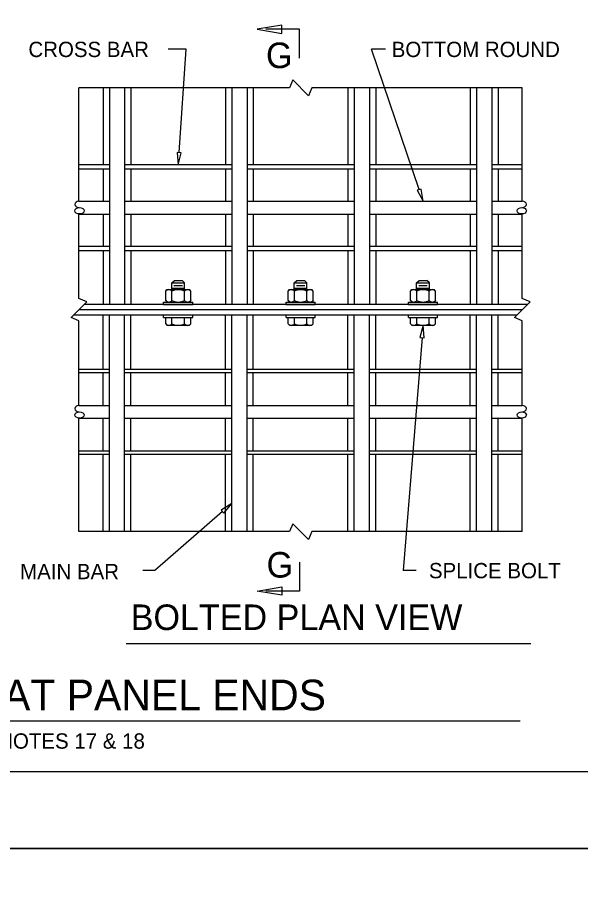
# Model space of a CAD drawing. Extents: x -24512 to -22484, y 4569 to 6351.
# Drawn here: x -23876.1 to -23765.7, y 5155.5 to 5325.8 of the extents above; entities that cross this region are included whole.
import ezdxf

# ---------------------------------------------------------------- set-up
doc = ezdxf.new("R2010")
doc.units = 0
for name, color, linetype in [('10', 7, 'Continuous'), ('2', 7, 'Continuous'), ('3', 7, 'Continuous'), ('4', 7, 'Continuous'), ('9', 7, 'Continuous'), ('PLT-BNDY', 7, 'Continuous')]:
    doc.layers.add(name, color=color, linetype=linetype)

msp = doc.modelspace()

# ---------------------------------------------------------------- linework, layer by layer
at = {"layer": '10'}
for p, q in [((-23775.46, 5203.08), (-23854.84, 5203.08)), ((-23777.59, 5187.94), (-23954.81, 5187.94))]:
    msp.add_line(p, q, dxfattribs=at)
for centre, major_axis, start_param, end_param in [((-23863.97, 5289.2), (0.895, 0), 1.692197, 4.591233), ((-23777.24, 5289.2), (-0.895, 0), 1.691952, 4.590988), ((-23863.97, 5249.2), (0.895, 0), 1.692197, 4.591233), ((-23777.24, 5249.2), (-0.895, 0), 1.691952, 4.590988)]:
    msp.add_ellipse(centre, major_axis=major_axis, ratio=0.699516, start_param=start_param, end_param=end_param, dxfattribs=at)
for centre, major_axis in [((-23863.97, 5287.95), (0.895, 0)), ((-23777.24, 5287.95), (-0.895, 0)), ((-23863.97, 5247.95), (0.895, 0)), ((-23777.24, 5247.95), (-0.895, 0))]:
    msp.add_ellipse(centre, major_axis=major_axis, ratio=0.699516, dxfattribs=at)
at = {"layer": '2'}
msp.add_line((-23353.75, 5178.04), (-24137.79, 5178.04), dxfattribs=at)
at = {"layer": '3'}
for points in [[(-23824.31, 5322.71), (-23824.31, 5324.33), (-23829.16, 5323.52)], [(-23824.31, 5214.25), (-23824.31, 5212.63), (-23829.16, 5213.44)]]:
    msp.add_lwpolyline(points, close=True, dxfattribs=at)
for points in [[(-23820.85, 5317.86), (-23820.85, 5323.52), (-23827.44, 5323.52)], [(-23820.85, 5219.1), (-23820.85, 5213.44), (-23827.44, 5213.44)]]:
    msp.add_lwpolyline(points, dxfattribs=at)
at = {"layer": '4'}
for p, q in [((-23864.08, 5289.82), (-23864.08, 5312.04)), ((-23859.32, 5312.04), (-23859.32, 5296.94)), ((-23858.09, 5312.04), (-23858.09, 5269.57)), ((-23855.12, 5312.04), (-23855.12, 5269.57)), ((-23853.89, 5312.04), (-23853.89, 5296.94)), ((-23835.33, 5312.04), (-23835.33, 5296.94)), ((-23834.09, 5312.04), (-23834.09, 5269.57)), ((-23831.12, 5312.04), (-23831.12, 5269.57)), ((-23829.89, 5312.04), (-23829.89, 5296.94)), ((-23811.33, 5312.04), (-23811.33, 5296.94)), ((-23810.09, 5312.04), (-23810.09, 5269.57)), ((-23807.12, 5312.04), (-23807.12, 5269.57)), ((-23805.89, 5312.04), (-23805.89, 5296.94)), ((-23787.33, 5312.04), (-23787.33, 5296.94)), ((-23786.09, 5312.04), (-23786.09, 5269.57)), ((-23783.12, 5312.04), (-23783.12, 5269.57)), ((-23781.89, 5312.04), (-23781.89, 5296.94)), ((-23777.14, 5289.82), (-23777.14, 5312.04)), ((-23858.09, 5296.94), (-23864.08, 5296.94)), ((-23834.09, 5296.94), (-23855.12, 5296.94)), ((-23810.09, 5296.94), (-23831.12, 5296.94)), ((-23786.09, 5296.94), (-23807.12, 5296.94)), ((-23777.14, 5296.94), (-23783.12, 5296.94)), ((-23864.08, 5296.19), (-23858.09, 5296.19)), ((-23859.32, 5296.19), (-23859.32, 5289.82)), ((-23855.12, 5296.19), (-23834.09, 5296.19)), ((-23853.89, 5296.19), (-23853.89, 5289.82)), ((-23835.33, 5296.19), (-23835.33, 5289.82)), ((-23831.12, 5296.19), (-23810.09, 5296.19)), ((-23829.89, 5296.19), (-23829.89, 5289.82)), ((-23811.33, 5296.19), (-23811.33, 5289.82)), ((-23807.12, 5296.19), (-23786.09, 5296.19)), ((-23805.89, 5296.19), (-23805.89, 5289.82)), ((-23787.33, 5296.19), (-23787.33, 5289.82)), ((-23783.12, 5296.19), (-23777.14, 5296.19)), ((-23781.89, 5296.19), (-23781.89, 5289.82)), ((-23864.08, 5289.82), (-23858.09, 5289.82)), ((-23855.12, 5289.82), (-23834.09, 5289.82)), ((-23831.12, 5289.82), (-23810.09, 5289.82)), ((-23807.12, 5289.82), (-23786.09, 5289.82)), ((-23783.12, 5289.82), (-23777.14, 5289.82)), ((-23864.08, 5287.32), (-23858.09, 5287.32)), ((-23859.32, 5287.32), (-23859.32, 5280.95)), ((-23855.12, 5287.32), (-23834.09, 5287.32)), ((-23853.89, 5287.32), (-23853.89, 5280.95)), ((-23835.33, 5287.32), (-23835.33, 5280.95)), ((-23831.12, 5287.32), (-23810.09, 5287.32)), ((-23829.89, 5287.32), (-23829.89, 5280.95)), ((-23811.33, 5287.32), (-23811.33, 5280.95)), ((-23807.12, 5287.32), (-23786.09, 5287.32)), ((-23805.89, 5287.32), (-23805.89, 5280.95)), ((-23787.33, 5287.32), (-23787.33, 5280.95)), ((-23783.12, 5287.32), (-23777.14, 5287.32)), ((-23781.89, 5287.32), (-23781.89, 5280.95)), ((-23858.09, 5280.95), (-23864.08, 5280.95)), ((-23864.08, 5280.2), (-23858.09, 5280.2)), ((-23859.32, 5280.2), (-23859.32, 5269.57)), ((-23834.09, 5280.95), (-23855.12, 5280.95)), ((-23855.12, 5280.2), (-23834.09, 5280.2)), ((-23853.89, 5280.2), (-23853.89, 5269.57)), ((-23835.33, 5280.2), (-23835.33, 5269.57)), ((-23810.09, 5280.95), (-23831.12, 5280.95)), ((-23831.12, 5280.2), (-23810.09, 5280.2)), ((-23829.89, 5280.2), (-23829.89, 5269.57)), ((-23811.33, 5280.2), (-23811.33, 5269.57)), ((-23786.09, 5280.95), (-23807.12, 5280.95)), ((-23807.12, 5280.2), (-23786.09, 5280.2)), ((-23805.89, 5280.2), (-23805.89, 5269.57)), ((-23787.33, 5280.2), (-23787.33, 5269.57)), ((-23777.14, 5280.95), (-23783.12, 5280.95)), ((-23783.12, 5280.2), (-23777.14, 5280.2)), ((-23781.89, 5280.2), (-23781.89, 5269.57)), ((-23845.86, 5273.82), (-23845.36, 5274.32)), ((-23845.36, 5274.32), (-23843.86, 5274.32)), ((-23843.36, 5273.82), (-23843.86, 5274.32)), ((-23821.86, 5273.82), (-23821.36, 5274.32)), ((-23821.36, 5274.32), (-23819.86, 5274.32)), ((-23819.36, 5273.82), (-23819.86, 5274.32)), ((-23797.86, 5273.82), (-23797.36, 5274.32)), ((-23797.36, 5274.32), (-23795.86, 5274.32)), ((-23795.36, 5273.82), (-23795.86, 5274.32)), ((-23847.06, 5272.18), (-23846.81, 5272.51)), ((-23846.81, 5272.51), (-23842.41, 5272.51)), ((-23845.86, 5273.82), (-23843.36, 5273.82)), ((-23845.86, 5272.51), (-23845.86, 5273.82)), ((-23845.86, 5272.82), (-23843.36, 5272.82)), ((-23845.44, 5273.32), (-23843.77, 5273.32)), ((-23843.36, 5272.51), (-23843.36, 5273.82)), ((-23842.15, 5272.18), (-23842.41, 5272.51)), ((-23823.06, 5272.18), (-23822.81, 5272.51)), ((-23822.81, 5272.51), (-23818.41, 5272.51)), ((-23821.86, 5272.51), (-23821.86, 5273.82)), ((-23821.86, 5273.82), (-23819.36, 5273.82)), ((-23821.86, 5272.82), (-23819.36, 5272.82)), ((-23821.44, 5273.32), (-23819.78, 5273.32)), ((-23819.36, 5272.51), (-23819.36, 5273.82)), ((-23818.15, 5272.18), (-23818.41, 5272.51)), ((-23799.06, 5272.18), (-23798.81, 5272.51)), ((-23798.81, 5272.51), (-23794.41, 5272.51)), ((-23797.86, 5273.82), (-23795.36, 5273.82)), ((-23797.86, 5272.51), (-23797.86, 5273.82)), ((-23797.86, 5272.82), (-23795.36, 5272.82)), ((-23797.44, 5273.32), (-23795.78, 5273.32)), ((-23795.36, 5272.51), (-23795.36, 5273.82)), ((-23794.15, 5272.18), (-23794.41, 5272.51)), ((-23847.06, 5270.39), (-23847.06, 5272.18)), ((-23845.83, 5270.39), (-23845.83, 5272.18)), ((-23843.38, 5270.39), (-23843.38, 5272.18)), ((-23842.15, 5270.39), (-23842.15, 5272.18)), ((-23823.06, 5270.39), (-23823.06, 5272.18)), ((-23821.83, 5270.39), (-23821.83, 5272.18)), ((-23819.38, 5270.39), (-23819.38, 5272.18)), ((-23818.15, 5270.39), (-23818.15, 5272.18)), ((-23799.06, 5270.39), (-23799.06, 5272.18)), ((-23797.83, 5270.39), (-23797.83, 5272.18)), ((-23795.38, 5270.39), (-23795.38, 5272.18)), ((-23794.15, 5270.39), (-23794.15, 5272.18)), ((-23776.14, 5269.57), (-23863.08, 5269.57)), ((-23847.47, 5269.57), (-23847.47, 5270.07)), ((-23847.47, 5270.07), (-23841.74, 5270.07)), ((-23847.47, 5269.57), (-23841.74, 5269.57)), ((-23847.06, 5270.39), (-23846.81, 5270.07)), ((-23846.81, 5270.07), (-23842.41, 5270.07)), ((-23842.15, 5270.39), (-23842.41, 5270.07)), ((-23841.74, 5269.57), (-23841.74, 5270.07)), ((-23823.47, 5270.07), (-23817.74, 5270.07)), ((-23823.47, 5269.57), (-23823.47, 5270.07)), ((-23823.47, 5269.57), (-23817.74, 5269.57)), ((-23823.06, 5270.39), (-23822.81, 5270.07)), ((-23822.81, 5270.07), (-23818.41, 5270.07)), ((-23818.15, 5270.39), (-23818.41, 5270.07)), ((-23817.74, 5269.57), (-23817.74, 5270.07)), ((-23799.47, 5269.57), (-23799.47, 5270.07)), ((-23799.47, 5270.07), (-23793.74, 5270.07)), ((-23799.47, 5269.57), (-23793.74, 5269.57)), ((-23799.06, 5270.39), (-23798.81, 5270.07)), ((-23798.81, 5270.07), (-23794.41, 5270.07)), ((-23794.15, 5270.39), (-23794.41, 5270.07)), ((-23793.74, 5269.57), (-23793.74, 5270.07)), ((-23865.08, 5267.57), (-23778.14, 5267.57)), ((-23777.14, 5268.57), (-23864.08, 5268.57)), ((-23859.32, 5256.95), (-23859.32, 5267.57)), ((-23858.09, 5225.1), (-23858.09, 5267.57)), ((-23855.12, 5225.1), (-23855.12, 5267.57)), ((-23853.89, 5256.95), (-23853.89, 5267.57)), ((-23847.47, 5267.07), (-23847.47, 5267.57)), ((-23847.47, 5267.57), (-23841.74, 5267.57)), ((-23841.74, 5267.07), (-23841.74, 5267.57)), ((-23835.33, 5256.95), (-23835.33, 5267.57)), ((-23834.09, 5225.1), (-23834.09, 5267.57)), ((-23831.12, 5225.1), (-23831.12, 5267.57)), ((-23829.89, 5256.95), (-23829.89, 5267.57)), ((-23823.47, 5267.57), (-23817.74, 5267.57)), ((-23823.47, 5267.07), (-23823.47, 5267.57)), ((-23817.74, 5267.07), (-23817.74, 5267.57)), ((-23811.33, 5256.95), (-23811.33, 5267.57)), ((-23810.09, 5225.1), (-23810.09, 5267.57)), ((-23807.12, 5225.1), (-23807.12, 5267.57)), ((-23805.89, 5256.95), (-23805.89, 5267.57)), ((-23799.47, 5267.07), (-23799.47, 5267.57)), ((-23799.47, 5267.57), (-23793.74, 5267.57)), ((-23793.74, 5267.07), (-23793.74, 5267.57)), ((-23787.33, 5256.95), (-23787.33, 5267.57)), ((-23786.09, 5225.1), (-23786.09, 5267.57)), ((-23783.12, 5225.1), (-23783.12, 5267.57)), ((-23781.89, 5256.95), (-23781.89, 5267.57)), ((-23847.47, 5267.07), (-23841.74, 5267.07)), ((-23847.06, 5265.83), (-23847.06, 5267.07)), ((-23847.06, 5265.83), (-23846.81, 5265.51)), ((-23845.83, 5265.83), (-23845.83, 5267.07)), ((-23843.38, 5265.83), (-23843.38, 5267.07)), ((-23842.15, 5265.83), (-23842.41, 5265.51)), ((-23842.15, 5265.83), (-23842.15, 5267.07)), ((-23823.47, 5267.07), (-23817.74, 5267.07)), ((-23823.06, 5265.83), (-23823.06, 5267.07)), ((-23823.06, 5265.83), (-23822.81, 5265.51)), ((-23821.83, 5265.83), (-23821.83, 5267.07)), ((-23819.38, 5265.83), (-23819.38, 5267.07)), ((-23818.15, 5265.83), (-23818.41, 5265.51)), ((-23818.15, 5265.83), (-23818.15, 5267.07)), ((-23799.47, 5267.07), (-23793.74, 5267.07)), ((-23799.06, 5265.83), (-23799.06, 5267.07)), ((-23799.06, 5265.83), (-23798.81, 5265.51)), ((-23797.83, 5265.83), (-23797.83, 5267.07)), ((-23795.38, 5265.83), (-23795.38, 5267.07)), ((-23794.15, 5265.83), (-23794.41, 5265.51)), ((-23794.15, 5265.83), (-23794.15, 5267.07)), ((-23846.81, 5265.51), (-23842.41, 5265.51)), ((-23822.81, 5265.51), (-23818.41, 5265.51)), ((-23798.81, 5265.51), (-23794.41, 5265.51)), ((-23864.08, 5256.95), (-23858.09, 5256.95)), ((-23858.09, 5256.2), (-23864.08, 5256.2)), ((-23859.32, 5249.82), (-23859.32, 5256.2)), ((-23855.12, 5256.95), (-23834.09, 5256.95)), ((-23834.09, 5256.2), (-23855.12, 5256.2)), ((-23853.89, 5249.82), (-23853.89, 5256.2)), ((-23835.33, 5249.82), (-23835.33, 5256.2)), ((-23831.12, 5256.95), (-23810.09, 5256.95)), ((-23810.09, 5256.2), (-23831.12, 5256.2)), ((-23829.89, 5249.82), (-23829.89, 5256.2)), ((-23811.33, 5249.82), (-23811.33, 5256.2)), ((-23807.12, 5256.95), (-23786.09, 5256.95)), ((-23786.09, 5256.2), (-23807.12, 5256.2)), ((-23805.89, 5249.82), (-23805.89, 5256.2)), ((-23787.33, 5249.82), (-23787.33, 5256.2)), ((-23783.12, 5256.95), (-23777.14, 5256.95)), ((-23777.14, 5256.2), (-23783.12, 5256.2)), ((-23781.89, 5249.82), (-23781.89, 5256.2)), ((-23864.08, 5249.82), (-23858.09, 5249.82)), ((-23855.12, 5249.82), (-23834.09, 5249.82)), ((-23831.12, 5249.82), (-23810.09, 5249.82)), ((-23807.12, 5249.82), (-23786.09, 5249.82)), ((-23783.12, 5249.82), (-23777.14, 5249.82)), ((-23864.08, 5225.1), (-23864.08, 5247.32)), ((-23864.08, 5247.32), (-23858.09, 5247.32)), ((-23859.32, 5240.95), (-23859.32, 5247.32)), ((-23855.12, 5247.32), (-23834.09, 5247.32)), ((-23853.89, 5240.95), (-23853.89, 5247.32)), ((-23835.33, 5240.95), (-23835.33, 5247.32)), ((-23831.12, 5247.32), (-23810.09, 5247.32)), ((-23829.89, 5240.95), (-23829.89, 5247.32)), ((-23811.33, 5240.95), (-23811.33, 5247.32)), ((-23807.12, 5247.32), (-23786.09, 5247.32)), ((-23805.89, 5240.95), (-23805.89, 5247.32)), ((-23787.33, 5240.95), (-23787.33, 5247.32)), ((-23783.12, 5247.32), (-23777.14, 5247.32)), ((-23781.89, 5240.95), (-23781.89, 5247.32)), ((-23777.14, 5225.1), (-23777.14, 5247.32)), ((-23864.08, 5240.95), (-23858.09, 5240.95)), ((-23858.09, 5240.2), (-23864.08, 5240.2)), ((-23859.32, 5225.1), (-23859.32, 5240.2)), ((-23855.12, 5240.95), (-23834.09, 5240.95)), ((-23834.09, 5240.2), (-23855.12, 5240.2)), ((-23853.89, 5225.1), (-23853.89, 5240.2)), ((-23835.33, 5225.1), (-23835.33, 5240.2)), ((-23831.12, 5240.95), (-23810.09, 5240.95)), ((-23810.09, 5240.2), (-23831.12, 5240.2)), ((-23829.89, 5225.1), (-23829.89, 5240.2)), ((-23811.33, 5225.1), (-23811.33, 5240.2)), ((-23807.12, 5240.95), (-23786.09, 5240.95)), ((-23786.09, 5240.2), (-23807.12, 5240.2)), ((-23805.89, 5225.1), (-23805.89, 5240.2)), ((-23787.33, 5225.1), (-23787.33, 5240.2)), ((-23783.12, 5240.95), (-23777.14, 5240.95)), ((-23777.14, 5240.2), (-23783.12, 5240.2)), ((-23781.89, 5225.1), (-23781.89, 5240.2))]:
    msp.add_line(p, q, dxfattribs=at)
for points in [[(-23777.14, 5312.04), (-23818.41, 5312.04), (-23819.06, 5310.49), (-23822.16, 5313.59), (-23822.8, 5312.04), (-23864.08, 5312.04)], [(-23864.08, 5249.82), (-23864.08, 5266.38), (-23865.63, 5267.02), (-23862.53, 5270.12), (-23864.08, 5270.76), (-23864.08, 5287.32)], [(-23777.14, 5249.82), (-23777.14, 5266.38), (-23778.69, 5267.02), (-23775.58, 5270.12), (-23777.14, 5270.76), (-23777.14, 5287.32)], [(-23777.14, 5225.1), (-23818.41, 5225.1), (-23819.06, 5223.55), (-23822.16, 5226.65), (-23822.8, 5225.1), (-23864.08, 5225.1)]]:
    msp.add_lwpolyline(points, dxfattribs=at)
for centre, radius, start, end in [((-23846.45, 5271.76), 0.743, 34.3959, 145.6041), ((-23844.61, 5270.02), 2.49, 60.4609, 119.5391), ((-23842.77, 5271.76), 0.743, 34.3959, 145.6041), ((-23822.45, 5271.76), 0.743, 34.3959, 145.6041), ((-23820.61, 5270.02), 2.49, 60.4609, 119.5391), ((-23818.77, 5271.76), 0.743, 34.3959, 145.6041), ((-23798.45, 5271.76), 0.743, 34.3959, 145.6041), ((-23796.61, 5270.02), 2.49, 60.4609, 119.5391), ((-23794.77, 5271.76), 0.743, 34.3959, 145.6041), ((-23846.45, 5270.81), 0.743, 214.3959, 325.6041), ((-23844.61, 5272.56), 2.49, 240.4609, 299.5391), ((-23842.77, 5270.81), 0.743, 214.3959, 325.6041), ((-23822.45, 5270.81), 0.743, 214.3959, 325.6041), ((-23820.61, 5272.56), 2.49, 240.4609, 299.5391), ((-23818.77, 5270.81), 0.743, 214.3959, 325.6041), ((-23798.45, 5270.81), 0.743, 214.3959, 325.6041), ((-23796.61, 5272.56), 2.49, 240.4609, 299.5391), ((-23794.77, 5270.81), 0.743, 214.3959, 325.6041), ((-23846.45, 5266.25), 0.743, 214.3959, 325.6041), ((-23844.61, 5268), 2.49, 240.4609, 299.5391), ((-23842.77, 5266.25), 0.743, 214.3959, 325.6041), ((-23822.45, 5266.25), 0.743, 214.3959, 325.6041), ((-23820.61, 5268), 2.49, 240.4609, 299.5391), ((-23818.77, 5266.25), 0.743, 214.3959, 325.6041), ((-23798.45, 5266.25), 0.743, 214.3959, 325.6041), ((-23796.61, 5268), 2.49, 240.4609, 299.5391), ((-23794.77, 5266.25), 0.743, 214.3959, 325.6041)]:
    msp.add_arc(centre, radius, start, end, dxfattribs=at)
at = {"layer": '9'}
for p, q in [((-23843.07, 5319.62), (-23846.57, 5319.62)), ((-23843.68, 5319.62), (-23846, 5319.62)), ((-23844.44, 5299.34), (-23843.07, 5319.62)), ((-23797.38, 5292.09), (-23806.69, 5319.62)), ((-23803.95, 5319.62), (-23806.69, 5319.62)), ((-23796.8, 5263.12), (-23800.53, 5217.5)), ((-23835.9, 5229.03), (-23849.18, 5217.5)), ((-23849.18, 5217.5), (-23851.57, 5217.5)), ((-23797.98, 5217.5), (-23800.53, 5217.5))]:
    msp.add_line(p, q, dxfattribs=at)
for points in [[(-23844.04, 5299.31), (-23844.84, 5299.37), (-23844.61, 5296.94)], [(-23797, 5292.22), (-23797.76, 5291.97), (-23796.61, 5289.82)], [(-23797.2, 5263.15), (-23796.4, 5263.08), (-23796.61, 5265.51)], [(-23836.17, 5229.33), (-23835.64, 5228.73), (-23834.09, 5230.6)]]:
    msp.add_lwpolyline(points, close=True, dxfattribs=at)
at = {"layer": 'PLT-BNDY'}
for points in [[(-24179.75, 5757.04), (-23338.75, 5757.04), (-23338.75, 5163.04), (-24179.75, 5163.04)], [(-24179.75, 5163.04), (-23338.75, 5163.04), (-23338.75, 4569.04), (-24179.75, 4569.04)]]:
    msp.add_lwpolyline(points, close=True, dxfattribs=at)

# ---------------------------------------------------------------- texts
at = {"layer": '10'}
msp.add_text('MAIN BAR SPLICE AT PANEL ENDS', height=6.0008, dxfattribs=at).set_placement((-23950.75, 5190.09))
at = {"layer": '9'}
for s, height, p in [('CROSS BAR', 3, (-23873.98, 5318.07)), ('G', 5, (-23827.4, 5315.91)), ('BOTTOM ROUND', 2.9999, (-23802.75, 5318.07)), ('G', 5, (-23827.29, 5216.09)), ('MAIN BAR', 3, (-23875.61, 5215.77)), ('SPLICE BOLT', 2.9999, (-23795.45, 5215.95)), ('BOLTED PLAN VIEW', 5, (-23853.92, 5205.82)), ('SEE NOTES 17 & 18', 2.9999, (-23889.05, 5182.57))]:
    msp.add_text(s, height=height, dxfattribs=at).set_placement(p)

doc.saveas('drawing.dxf')
